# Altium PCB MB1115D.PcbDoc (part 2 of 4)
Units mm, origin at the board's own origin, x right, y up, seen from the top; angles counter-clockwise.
Board outline 66 x 97 mm, 2 copper layers (TOP, Bottom), stack 1.535 mm thick; 198 components, 186 nets, 760 pads, 493 vias.
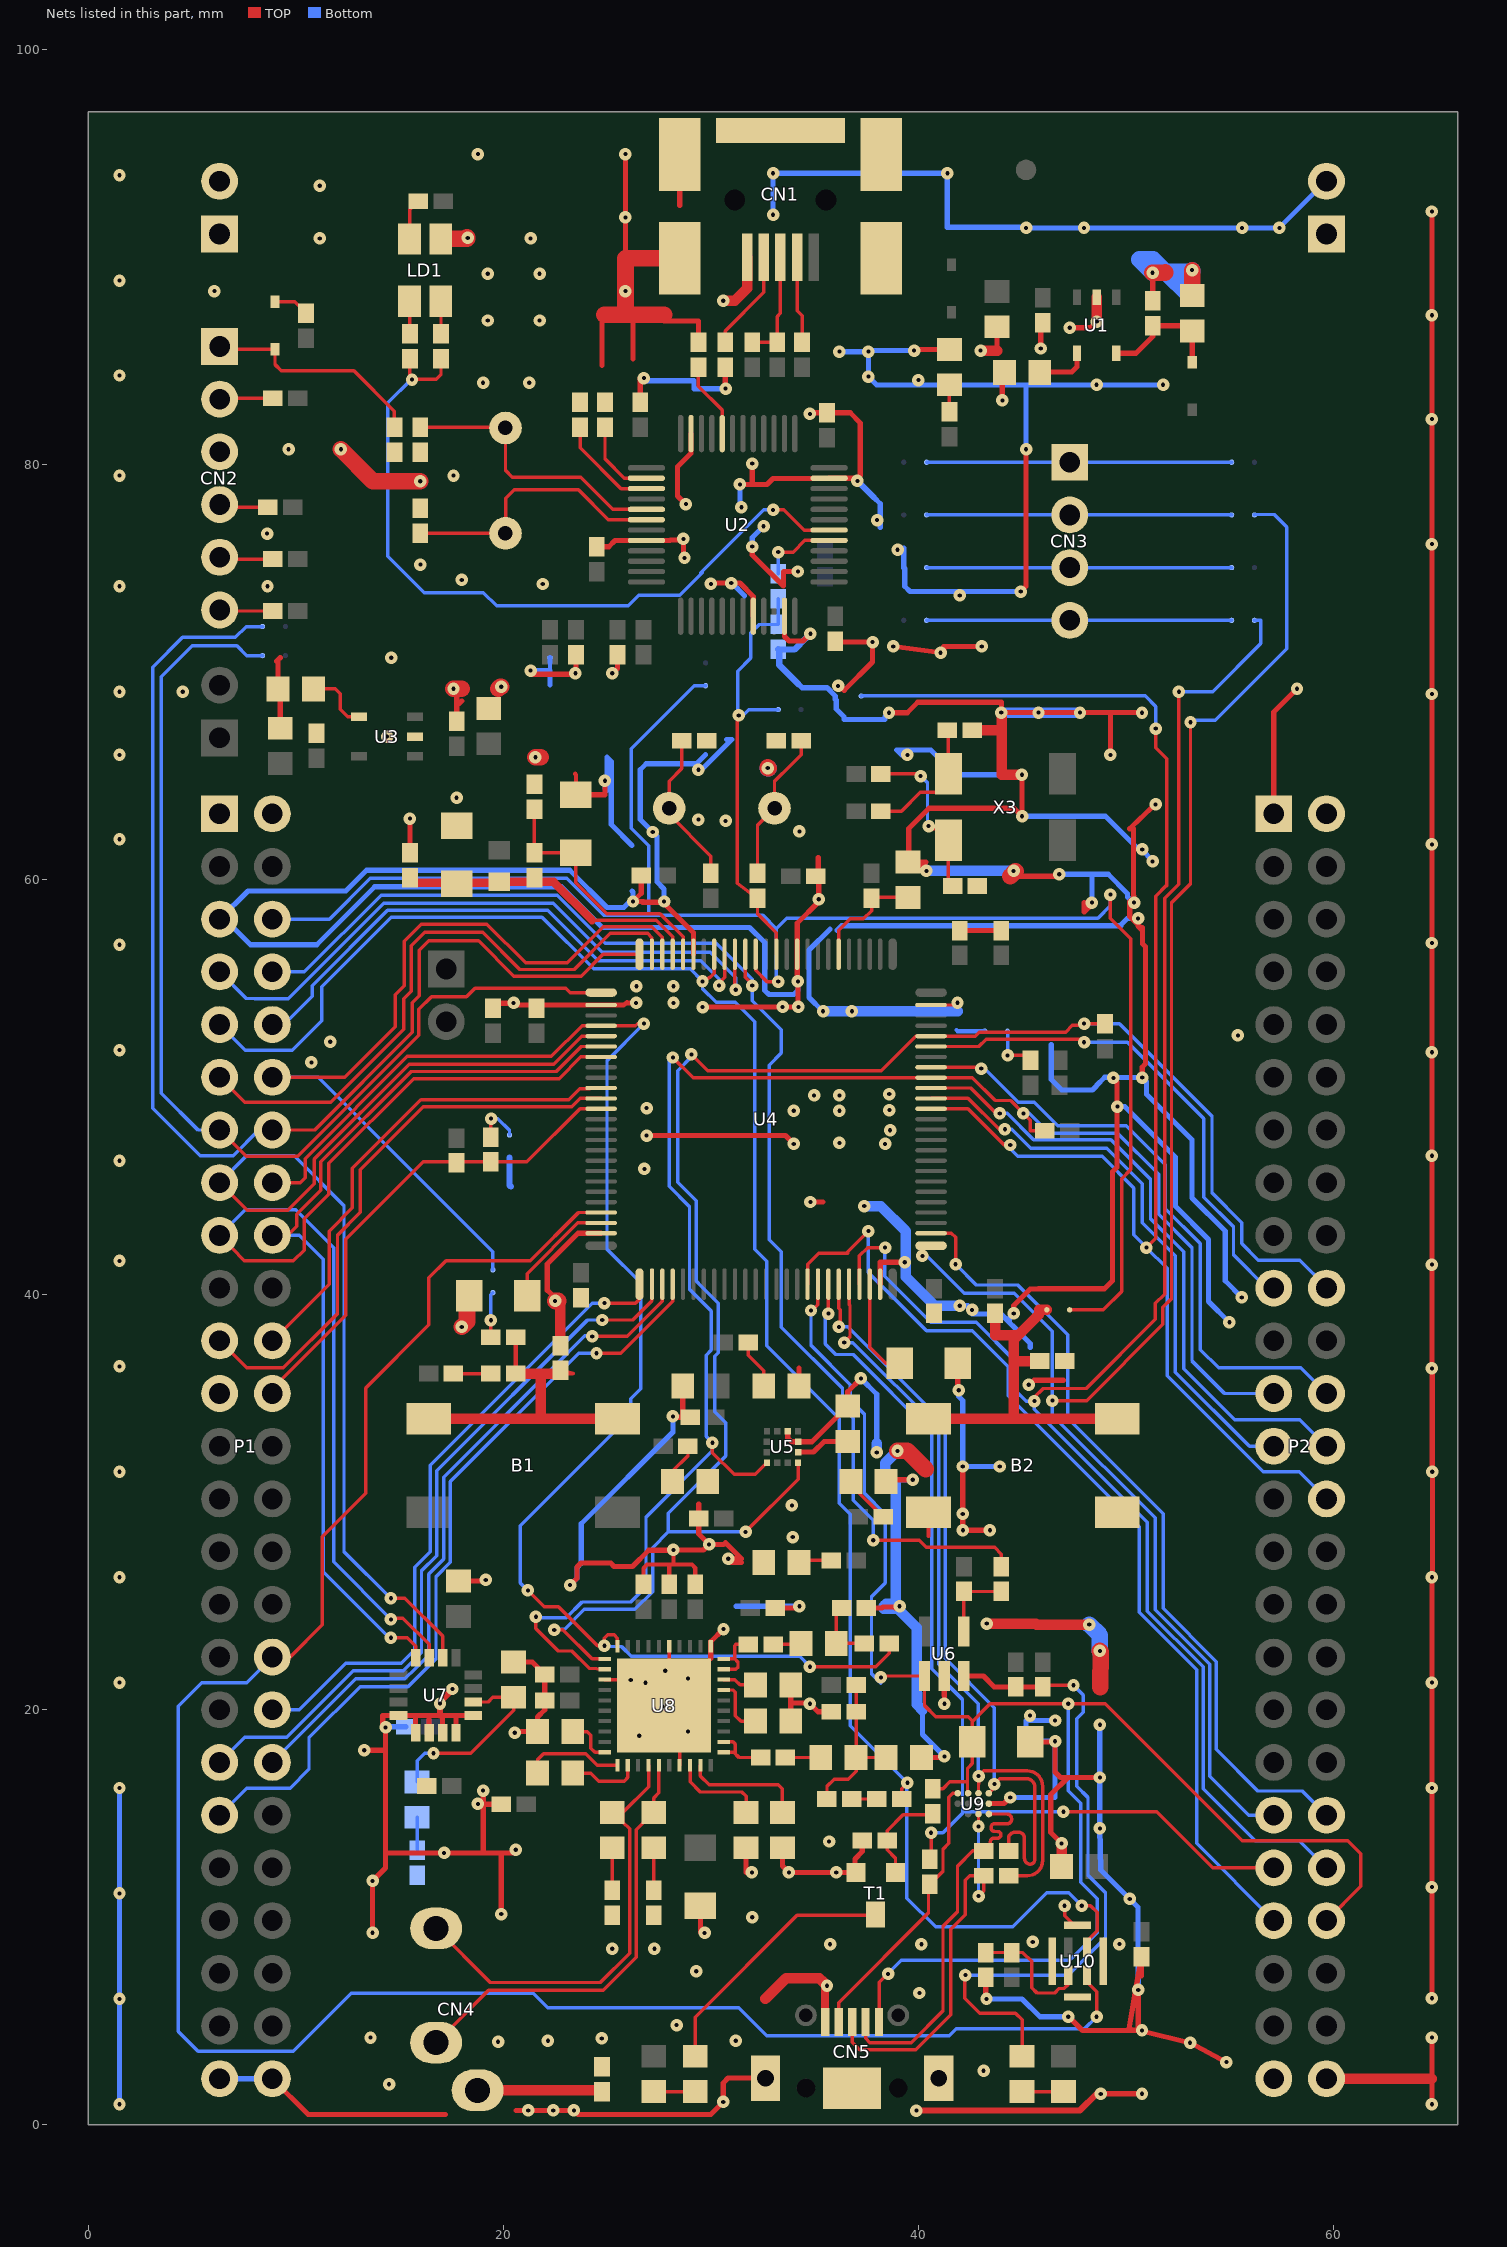
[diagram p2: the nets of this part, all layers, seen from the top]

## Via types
v1: diameter 0.6, hole 0.2, TOP to Bottom, tented both sides, 492 vias
v2: diameter 0.6, hole 0.2, TOP to Bottom, tented bottom, 1 vias

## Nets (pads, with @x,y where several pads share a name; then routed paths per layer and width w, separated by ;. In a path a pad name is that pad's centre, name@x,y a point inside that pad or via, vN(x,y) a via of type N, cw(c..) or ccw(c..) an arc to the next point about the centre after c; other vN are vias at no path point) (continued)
GND: B2.2 B2.3 C1.1 C2.1 C3.1 C4.2 C5.1 C6.1 C7.1 C8.1 C9.1 C10.1 C11.1 C12.2 C13.1 C14.2 C15.1 C16.1 C17.1 C18.1 C19.1 C20.2 C21.1 C22.2 C23.1 C24.2 C25.1 C26.2 C27.2 C28.2 C29.1 C30.1 C31.1 C32.1 C33.2 C34.1 C35.2 C37.1 C38.2 C39.1 C40.1 C41.1 C42.1 C43.1 C44.1 C45.1 C46.1 C48.1 C49.2 C50.1 C51.1 C52.2 C53.1 C54.2 C55.1 C58.2 C59.1 C62.1 C63.1 C64.2 C65.1 C66.1 C67.2 C68.1 CN1.5 CN1.6 CN1.7 CN1.8 CN1.9 CN1.10 CN2.3 CN5.5 CN5.6 CN5.7 CN5.8 JP3.1 JP3.2 JP4.1 JP4.2 LD1.1 LD2.2 LD3.2 LD4.2 LD5.2 LD6.2 P1.1 P1.2 P1.5 P1.23 P1.49 P1.50 P2.1 P2.2 P2.49 P2.50 R5.1 R6.2 R11.1 R12.1 R14.2 R19.1 R35.1 R43.2 R44.2 R50.2 R55.2 R59.2 R60.1 R61.1 R63.1 R68.2 SB6.2 SB12.1 SB19.1 SB20.1 T1.2 U1.2 U2.8 U2.20 U2.23 U2.35 U2.47 U3.2 U4.10 U4.20 U4.27 U4.49 U4.74 U4.99 U5.6 U5.8 U6.2 U7.8 U7.9 U7.10 U7.11 U7.12 U7.13 U8.3 U8.17 U8.31 U8.35 U8.41 U9.D2 U10.5 U10.6 U10.7 U10.8 | length 875.6
  TOP w0.165: U8.3@24.88,21.45 26.025,21.45 U8.41@26.04,21.435 ; U8.41@27.75,21.74 28,21.99 U8.35@28,23.07 ; U8.17@28.5,17.33 28.5,20.2 U8.41@27.75,20.2 28.964,21.414 30,22.45 30,22.476 ; U4.99@40.614,53.962 v1@41.89,53.962 ; v1@41.89,53.947 v1@41.89,53.962 ; v1(41.89,54.074) v1@41.89,53.962 ; v1(47.05,10.553) 47.05,10.08 47.519,9.611 U10.5@47.683,9.611
  TOP w0.2: C6.1@15.931,80.6 C6.1@15.962,80.6 ; 23.47,65.11 23.47,65.09 23.5,65.06 C22.2@23.5,64.097 ; C44.1@26.75,26.05 26.75,26.818 26.929,26.998 28,26.998 ; C45.1@28,26.05 28,26.998 ; v1(28.2,27.7) 28.2,27.683 28.2,26.998 ; C46.1@29.25,26.05 29.25,26.836 29.088,26.998 28.2,26.998 ; 40.49,28.38 B2.2@40.49,29.523 ; 28,26.998 28.2,26.998
  TOP w0.25: P1.50@8.87,2.22 10.599,0.491 17.208,0.491 ; C14.2@9.25,67.3 9.25,69.2 C13.1@9.15,69.2 9.15,70.6 9.075,70.525 9.25,70.7 ; v1(13.3,18.05) 14.331,18.05 ; v1(13.7,9.25) v1(13.7,11.75) ; v1(13.7,11.75) 14.331,12.381 14.331,13.1 ; C23.1@15.5,61.3 v1(15.5,62.948) ; U7.9@15.775,18.9 15.775,19.725 ; U7.10@16.425,18.9 16.425,19.725 ; U7.11@17.075,18.9 17.075,19.725 ; U7.12@17.725,18.9 17.725,19.725 ; C16.1@17.76,67.628 v1@17.76,69.2 ; 17.888,68.501 17.996,68.608 18,68.613 ; U7.13@18.55,19.725 17.725,19.725 ; v1(18.776,15.466) v1@19.03,15.466 ; v1(19.03,16.101) v1@19.03,15.466 ; v1(19.157,26.261) 19.096,26.2 C43.1@17.85,26.2 ; C31.1@19.5,53.8 19.75,54.05 20.5,54.05 20.588,53.962 21.589,53.962 C32.1@21.671,53.962 ; v1(19.9,10.15) 19.9,13.1 ; C59.1@19.9,15.45 v1@19.03,15.45 ; C48.1@20.5,22.3 21.4,22.3 C49.2@22,21.7 C50.1@22,20.45 22,19.998 21.65,19.648 C52.2@21.65,18.95 20.554,18.95 v1(20.554,18.895) ; v1(20.6,13.25) 20.45,13.1 19.9,13.1 ; 20.606,0.691 v1(21.206,0.691) v1(22.405,0.691) v1(23.405,0.691) 23.605,0.491 30.002,0.491 30.592,1.082 30.6,1.089 v1(30.6,1.1) 30.6,2.017 30.833,2.25 CN5.7@32.635,2.25 ; v1(21.316,70.076) 21.316,69.898 23.475,69.898 v1(23.475,69.949) 23.5,69.974 C11.1@23.5,70.85 ; C32.1@21.583,54.05 C32.1@21.671,53.962 ; v1@22.637,39.7 22.116,40.221 22.116,41.476 23.602,42.961 U4.49@24.714,42.962 ; v1(23.221,26.007) 23.551,26.337 23.551,26.883 23.742,27.074 25.177,27.074 25.342,26.909 26.231,26.909 27.006,27.683 v1@28.2,27.683 ; C22.2@23.5,64.097 24.9,64.097 v1(24.9,64.77) v1@24.9,64.8 ; C10.1@24.5,76.05 25.08,76.05 25.38,76.35 28.034,76.35 28.053,76.369 28.625,76.369 v1(28.682,76.426) 28.682,75.562 v1(28.733,75.512) ; v1(24.745,4.163) v1@24.75,4.158 ; 24.75,84.795 24.75,87.221 24.859,87.221 ; v1@25.25,8.484 v1(25.253,8.481) ; v1(25.253,69.949) 25.253,69.936 25.5,70.183 R19.1@25.5,70.85 ; 25.888,89.951 v1(25.888,91.92) v1(25.888,94.968) ; U8.41@26.04,21.435 v1(26.142,21.435) ; 26.25,85.095 26.25,87.221 ; v1(26.403,54.064) 25.958,54.071 25.8,53.962 U4.27@24.714,53.962 C32.1@21.671,53.962 ; C7.1@26.6,83 26.6,84.173 v1(26.777,84.173) ; C25.1@26.65,60.2 26.65,59.35 v1(26.25,58.95) 26.751,58.95 26.714,58.913 v1@27.818,58.913 ; v1(26.904,47.667) 33.6,47.667 v1(34,47.267) ; v1@27.25,8.446 v1(27.285,8.481) ; v1(27.666,20.165) 27.653,20.165 27.66,20.159 27.684,20.134 27.691,20.141 U8.41@27.75,20.2 27.75,21.74 27.75,21.88 v1(27.803,21.88) ; v1(27.75,58.95) 27.754,58.95 27.768,58.963 v1@27.818,58.913 ; 27.75,87.221 27.75,86.92 29.4,86.92 R5.1@29.4,85.9 ; v1@28.15,27.7 v1(28.2,27.7) 29.656,27.7 v1(29.921,27.965) ; v1(28.174,34.135) 28.174,34.097 28.177,34.1 C40.1@28.65,34.1 ; 28.506,92.504 CN1.7@28.506,94.951 ; C37.1@28.65,35.6 C40.1@28.65,34.1 ; v1(28.8,78.1) 28.401,78.499 28.401,79.9 29.05,80.549 U2.47@29.05,81.5 ; C40.1@29,34.1 C40.1@28.65,34.1 ; U4.20@29.164,56.412 29.164,57.449 27.818,58.794 v1@27.818,58.913 ; 29.42,29.923 C42.1@29.42,29.21 29.42,28.467 v1(29.921,27.965) ; C64.2@29.5,10.553 29.5,9.281 29.66,9.281 v1(29.698,9.243) ; v1(29.602,53.864) v1(33.457,53.871) v1@34.2,53.864 ; 30,22.476 30,23.274 v1(30.612,23.886) ; v1(30.002,74.253) 30.048,74.3 31.401,74.3 32.05,73.651 U2.20@32.05,72.7 ; R6.2@30.7,84.7 30.7,83.665 v1(30.714,83.665) ; v1(31.401,79.051) 32.001,79.051 ; 31.476,27.1 30.841,27.1 v1(30.841,27.277) 31.476,27.277 30.703,28.05 30.618,27.965 v1(29.921,27.965) ; C62.1@31.7,13.35 31.7,12.164 v1(31.984,12.164) ; v1(32.001,76.052) 32.001,75.653 33.501,74.152 33.501,74.853 v1(34.199,74.853) ; v1(32.001,80.05) 32.001,79.051 ; R43.2@33.1,24.9 34.179,24.9 v1(34.27,24.991) ; C63.1@33.45,13.35 33.45,12.476 v1(33.762,12.164) v1(36.048,12.164) 36.974,12.164 T1.2@36.976,12.166 ; U2.23@33.55,72.7 33.55,71.714 33.766,71.498 34.443,71.498 v1(34.799,71.855) ; U5.8@33.706,33.426 33.706,33.102 33.894,32.914 U5.6@34.218,32.914 34.88,32.914 C41.1@36.598,34.632 36.598,35.328 v1(37.236,35.966) ; C53.1@33.85,19.45 33.968,19.568 33.85,19.686 33.85,20.33 ; C51.1@33.85,21.194 33.85,20.33 ; 34.164,57.9 U4.10@34.164,56.412 34.164,55.071 v1@34.2,55.034 ; v1(34.2,55.1) v1@34.2,55.034 ; v1(34.219,53.871) v1@34.2,53.864 ; LD3.2@34.25,35.6 34.25,36.475 ; v1(34.778,82.449) 34.829,82.5 C8.1@35.54,82.5 ; v1(34.799,44.468) 35.399,44.468 ; C26.2@35.061,60.17 C26.2@35.182,60.17 ; 35.182,61.07 C26.2@35.182,60.17 ; v1(35.199,59.061) 35.199,60.17 C26.2@35.182,60.17 ; C8.1@35.6,82.5 36.718,82.5 37.204,82.014 37.204,79.474 v1@37.064,79.334 ; U2.35@35.7,79.35 37.064,79.35 v1@37.064,79.334 ; R50.2@35.8,19.9 35.17,19.9 v1(34.778,20.292) 34.816,20.33 33.85,20.33 ; C12.2@36,71.5 36,71.455 v1(37.798,71.455) 37.798,70.498 36.429,69.129 36.429,69.187 36.277,69.187 36.137,69.327 v1(36.137,69.339) ; T1.2@36.997,12.166 T1.2@36.976,12.166 ; v1(37.064,79.22) v1@37.064,79.334 ; R55.2@37.3,13.7 37.3,13.164 36.947,12.812 36.947,12.328 36.891,12.272 36.785,12.166 T1.2@36.976,12.166 ; R44.2@37.5,24.9 38.245,24.9 38.295,24.95 38.845,24.95 38.918,24.877 39.096,24.877 v1(39.096,24.991) ; U4.74@38.164,40.512 38.164,41.564 v1(39.35,41.564) ; LD5.2@38.45,31 38.45,31.087 39.477,31.087 v1(39.731,31.087) ; v1(38.588,68.044) 39.464,68.044 39.972,68.552 44.011,68.552 44.011,68.056 v1(45.793,68.056) v1(47.792,68.056) 49.256,68.056 ; v1(38.791,71.244) 38.86,71.235 41.019,70.947 v1(41.077,70.94) 41.225,70.94 41.225,71.244 v1(43.058,71.244) ; C27.2@39.5,60.85 C27.2@39.541,60.85 ; v1(39.8,85.5) 39.8,85.55 LD2.2@41.5,85.55 ; C58.2@40.15,17.7 41.178,17.7 41.242,17.765 v1(41.255,17.752) ; v1(40.391,60.424) 40.391,60.55 C27.2@40.075,60.55 ; B2.2@40.49,29.523 40.48,29.533 B2.2@40.569,29.533 ; U6.2@41.25,21.625 41.25,20.693 41.255,20.688 v1(41.255,20.292) ; C38.2@41.897,36.7 41.897,35.4 v1(41.95,35.4) ; C29.1@42,57.55 C30.1@44,57.55 ; v1(42.144,31.722) v1(42.144,29.436) 42.144,28.656 v1(42.15,28.65) v1(43.45,28.65) ; R61.1@43.25,7.1 43.25,6.105 v1(43.287,6.068) ; U9.D2@43.4,15.475 44.134,15.475 v1(44.43,15.771) ; 43.8,85.5 C1.1@43.8,86.65 ; v1(44.05,83.1) 44.05,84.45 C5.1@44.15,84.45 ; v1@44.437,60.17 46.647,60.17 46.696,60.218 46.741,60.264 v1(46.793,60.26) ; v1(44.594,60.424) 44.598,60.424 v1@44.684,60.417 ; v1(44.6,39.1) 44.6,39.477 45.394,40.271 45.793,40.271 45.808,40.285 48.977,40.285 49.362,40.67 49.362,45.925 49.577,46.14 v1@49.577,49.251 ; v1(44.938,73.886) 45.192,74.14 v1(45.192,80.744) ; v1(44.994,65.058) 44.994,63.059 44.606,63.447 40.518,63.447 39.541,62.469 C27.2@39.541,60.85 ; v1(45.319,35.659) 45.37,35.659 45.586,35.875 46.995,35.875 ; C54.2@45.397,18.45 v1@46.593,18.45 ; v1(45.9,85.6) 45.9,86.85 C2.1@46,86.85 ; v1(46.593,18.482) v1@46.593,18.45 ; C65.1@46.9,12.45 46.9,12.443 46.938,12.443 C65.1@46.95,12.443 ; v1(46.907,13.561) 46.795,13.673 46.386,14.082 46.386,15.91 47.211,16.736 ; v1@47.235,5.218 47.908,4.544 v1@50.585,4.544 ; v1(47.3,86.6) 48.3,86.6 v1(48.6,86.9) ; 48,58.9 48,58.444 48.411,58.856 v1(48.367,58.9) ; v1(48.748,16.736) 47.211,16.736 ; v1(48.792,1.49) v1(48.792,1.49) 50.704,1.496 v1(50.78,1.496) ; v1(49.256,66.012) 49.256,68.056 ; v1(49.4,50.45) 49.4,50.427 49.577,50.251 v1@49.577,49.251 ; v1(49.592,49.066) 49.591,49.074 v1@49.577,49.251 ; 50.374,59.235 50.374,59.243 ; v1(50.4,58.9) v1@50.4,59.09 ; v1(50.59,58.138) 50.59,57.833 ; v1(50.6,6.5) 50.6,4.724 v1(50.78,4.544) ; 50.75,7.173 C66.1@50.75,8.1 50.478,6.521 50.15,4.616 v1@50.585,4.544 ; v1(50.78,68.044) 50.768,68.056 49.256,68.056 ; v1(50.791,50.465) 50.791,50.965 50.953,51.128 50.953,56.766 50.805,56.914 50.805,57.554 ; 50.805,57.693 50.805,57.617 ; C3.1@51.3,87.9 v1@51.3,89.253 ; v1@51.44,63.624 51.391,63.624 51.348,63.583 50.191,62.459 50.374,62.459 50.374,59.243 ; v1(54.844,3.02) v1(53.1,3.95) 53.006,3.973 v1@50.869,4.497 ; P2.1@57.13,63.18 57.13,68.08 v1(58.25,69.2) ; v1(64.75,0.988) 64.75,2.22 v1(64.75,4.2) v1@64.75,4.3 ; v1(64.75,6.1) v1(64.75,11.45) v1(64.75,16.228) v1(64.75,21.308) v1(64.75,26.388) 64.775,26.388 64.775,31.463 v1(64.77,31.468) 64.77,36.429 v1(64.75,36.449) v1(64.75,41.45) v1(64.75,46.7) v1(64.75,51.689) v1(64.75,56.95) v1(64.75,61.7) v1(64.75,68.95) v1(64.75,76.172) v1(64.75,82.2) v1(64.75,87.2) v1@64.75,92.2 ; 14.331,13.1 14.331,18.05 ; 14.331,13.1 v1(17.15,13.1) 19.03,13.1 ; 14.331,18.05 v1(14.331,19.149) 14.191,19.149 14.191,19.725 U7.8@14.95,19.725 15.775,19.725 ; 15.775,19.725 16.425,19.725 ; 16.425,19.725 16.942,19.725 17.075,19.725 ; 17.075,19.725 17.725,19.725 ; C43.1@17.85,26.2 17.798,26.2 17.798,26.252 C43.1@17.85,26.2 ; 19.03,13.1 19.9,13.1 ; 19.03,13.1 v1@19.03,15.45 ; v1@19.03,15.45 v1@19.03,15.466 ; v1@19.03,15.45 19.014,15.45 v1@19.03,15.466 ; 32.001,79.051 32.712,79.051 33,79.339 35.651,79.339 35.7,79.339 36.998,79.334 v1@37.064,79.334 ; v1@34.2,53.864 v1@34.2,55.034 ; C27.2@39.541,60.85 40.375,60.85 C27.2@40.075,60.55 ; C27.2@39.541,60.85 39.541,60.55 C27.2@40.075,60.55 ; v1@46.593,18.45 46.593,17.003 46.86,16.736 47.211,16.736 ; 50.374,59.243 50.4,59.216 v1@50.4,59.09 ; v1@50.4,59.09 50.336,59.09 50.273,59.027 50.191,58.946 50.191,58.231 50.437,57.986 50.59,57.833 ; v1@50.585,4.544 50.775,4.513 50.794,4.51 v1@50.869,4.497 ; v1@50.585,4.544 v1(50.78,4.544) ; 50.59,57.833 50.59,57.77 50.805,57.554 ; 50.59,57.833 50.805,57.617 ; v1(50.78,4.544) 50.795,4.536 v1@50.869,4.497 ; 50.805,57.554 50.805,57.617
  TOP w0.254: 34.164,57.9 35.199,58.935 v1(35.199,59.061)
  TOP w0.305: 16.942,19.725 16.95,19.733 v1(16.95,20.3) 16.95,20.4 v1(17.55,21) ; v1@39.898,0.691 47.792,0.691 48.592,1.49 v1(48.792,1.49)
  TOP w0.381: CN5.5@35.51,4.95 35.51,6.61 v1(35.6,6.7)
  TOP w0.4: C32.1@21.583,54.05 21.589,53.962 C32.1@21.6,53.8 ; C8.1@35.54,82.5 C8.1@35.6,82.5
  TOP w0.5: v1@22.726,39.7 22.75,39.7 R35.1@22.75,37.55 ; C34.1@23.65,39.7 C34.1@23.677,39.673
  TOP w0.508: C6.1@15.931,80.6 15.962,80.569 C6.1@15.962,80.6 ; v1(30.6,87.9) 31.156,87.9 31.756,88.5 CN1.5@31.756,90.001 ; 32.635,6.078 33.626,7.069 35.231,7.069 35.396,6.904 v1(35.6,6.7) ; C20.2@42.6,67.2 44.011,67.2 ; v1(43,85.5) 43.8,85.5 ; v1(43.3,24.15) 43.307,24.15 45.649,24.153 45.7,24.102 v1(48.24,24.102) v1@48.24,24.153 ; v1@44.011,68.056 44.011,67.2 ; v1(44.994,65.058) 44.011,65.058 44.011,67.2 ; v1(46.907,13.561) 46.907,12.475 46.916,12.466 C65.1@46.938,12.443 ; U1.2@48.599,88.071 v1(48.6,86.9) ; P2.50@59.67,2.22 64.75,2.22
  TOP w0.8: v1(12.172,80.744) 13.716,79.2 v1(16,79.2) ; LD1.1@16.986,90.88 18.25,90.88 v1@18.25,90.95 ; v1(17.6,69.2) 17.76,69.2 18,69.2 ; v1@18,38.45 18.25,38.7 18.25,39.95 C33.2@18.353,39.95 ; v1@19.75,69.2 19.85,69.3 v1(19.9,69.3) ; v1(21.55,65.9) v1@21.8,65.9 ; v1(22.5,39.7) v1@22.637,39.7 ; 24.859,87.221 25.888,87.221 ; 25.888,89.951 25.952,89.951 ; 27.75,87.221 26.25,87.221 25.888,87.221 ; CN1.6@28.506,89.951 25.952,89.951 ; v1(32.746,65.377) 32.784,65.377 32.765,65.396 v1@32.75,65.411 ; C51.1@33.85,21.194 C51.1@33.85,21.2 ; v1(38.997,32.475) 39.474,32.475 40.366,31.582 ; B2.2@40.366,29.566 40.4,29.533 40.49,29.533 B2.2@40.569,29.533 ; v1@44.437,60.17 44.642,60.376 v1@44.684,60.417 ; v1@48.748,22.832 48.792,22.788 48.771,21.093 ; v1(51.288,89.253) 51.3,89.253 51.9,89.265 ; v1(53.193,89.38) 53.2,89.373 C4.2@53.2,88.15 ; 25.888,87.221 v1(25.888,88.364) 25.888,89.888 25.952,89.951
  Bottom w0.165: v1(14.331,19.149) v1@14.359,19.177 ; 41.89,53.664 v1(41.89,54.074)
  Bottom w0.2: 22.24,69.38 22.25,69.39 ; 22.25,70.076 22.25,70.48 ; 41.84,52.75 41.89,52.7 SB19.1@43.2,52.7
  Bottom w0.25: v1(1.504,0.988) v1(1.504,6.068) v1(1.504,11.148) v1(1.504,16.228) ; P1.49@6.33,2.22 P1.50@8.87,2.22 ; v1@14.359,19.177 C68.1@15.31,19.177 ; v1@21.341,70.076 22.25,70.076 22.25,69.39 ; 22.25,70.48 SB12.1@22.25,70.7 ; v1(23.221,26.007) 23.551,26.337 23.551,26.858 23.754,27.061 23.754,28.966 28.174,33.386 ; v1@24.9,64.8 v1(24.9,64.77) 24.9,64.4 25,64.3 25,65.9 25.2,65.7 25.2,62.656 26.2,61.656 ; 26.2,59.461 26.25,59.411 v1(26.25,58.95) 26.171,59.029 25.804,58.661 25.004,58.661 23.205,60.46 13.41,60.46 12.411,59.461 7.691,59.461 P1.5@6.33,58.1 6.575,58.1 7.813,56.862 11.011,56.862 13.81,59.661 22.805,59.661 24.766,57.7 31.87,57.7 32.6,56.97 32.6,54.663 32.8,54.463 34,54.463 34.2,54.663 v1(34.2,55.1) ; v1@26.675,84.046 29.19,84.046 29.19,83.665 v1(30.714,83.665) ; v1(27.75,58.95) 27.75,59.553 27.403,59.9 27.403,62.099 v1(27.2,62.3) 26.6,62.902 26.6,65.3 26.886,65.586 29.31,65.586 29.749,66.025 ; 28.174,33.373 28.174,33.386 ; v1(28.174,34.135) 28.174,33.386 ; v1@29.55,65.3 31.007,66.757 30.765,66.757 ; v1@30.581,23.854 v1(30.612,23.886) ; v1@31,74.3 31.018,74.3 31.628,73.689 ; 31.222,24.991 v1(34.27,24.991) ; v1(31.401,79.051) 31.401,78.025 v1(31.476,77.95) ; v1(32.001,76.052) 32.001,76.493 v1(32.543,77.036) ; v1(33,92.044) v1(33,94.043) 41.396,94.043 41.396,91.445 45.16,91.445 v1(45.192,91.412) v1(47.986,91.412) v1(55.606,91.412) v1@57.384,91.412 ; 34.229,69.426 34.399,69.256 35.599,69.256 36,68.855 36,68.7 36.048,68.652 36.048,68.222 36.413,67.857 36.413,67.714 38.401,67.714 38.401,67.857 v1(38.588,68.044) v1@38.6,68.056 ; v1@34.27,24.864 v1(34.27,24.991) ; v1@34.397,24.991 v1(34.27,24.991) ; 34.585,71.64 v1(34.799,71.855) ; v1@35.399,53.664 34.735,54.328 34.735,56.614 35.738,57.617 ; 36.086,57.566 36.302,57.782 49.764,57.782 49.764,57.833 50.069,58.138 50.221,58.138 ; v1(36.198,85.448) v1(37.598,85.448) ; v1(37.236,35.966) 37.997,35.205 37.997,32.83 ; 37.828,78.456 37.864,78.42 38.169,78.115 38.169,76.976 ; v1@37.997,32.403 v1(38,32.4) ; 38.613,31.087 v1(39.731,31.087) ; 39.299,75.989 SB6.2@39.299,75.041 39.35,74.99 39.35,74.14 39.604,73.886 v1(44.938,73.886) ; v1(39.35,41.564) v1@39.397,41.564 ; v1(39.477,66.012) 39.203,66.012 38.957,66.257 40.596,66.257 41.796,65.058 v1(44.994,65.058) ; v1(39.8,85.5) 37.65,85.5 v1(37.598,85.448) ; 39.95,20.3 39.952,20.298 ; v1@39.996,84.048 v1@39.996,83.848 ; 40.196,19.987 40.196,18.811 v1(41.255,17.752) ; v1(41.95,35.4) 41.95,35.091 42.144,34.897 v1(42.144,31.722) v1(43.922,31.722) ; v1(41.995,39.471) 42.395,39.471 v1(42.595,39.271) 42.595,39.071 43.979,39.071 44.4,38.65 ; v1(43.287,6.068) 45,6.068 45.861,5.207 v1(47.224,5.207) ; v1(44.43,15.771) 46.576,15.771 46.593,15.788 v1(46.593,18.482) 45.194,18.482 45.194,19.481 v1(46.593,19.481) ; v1(44.6,39.1) 44.4,38.9 44.4,38.65 ; v1@44.994,63.059 v1(45,63.059) 49.021,63.059 50.62,61.46 v1(50.791,61.46) v1(51.288,60.881) ; v1(45.192,80.744) 45.192,83.848 ; 45.394,37.472 45.394,37.656 44.635,38.415 44.4,38.65 ; 46.411,52.053 46.411,50.366 46.911,49.866 48.392,49.866 48.592,50.066 48.592,50.083 48.989,50.48 49.4,50.48 v1(49.4,50.45) 49.415,50.465 v1(50.791,50.465) 50.793,50.463 50.991,50.266 50.991,49.666 53.19,47.467 53.19,44.668 54.789,43.069 54.789,40.67 v1(55.588,39.871) ; v1(46.793,60.26) 48.367,60.26 ; v1(48.367,58.9) 48.367,60.26 ; v1(48.748,19.276) v1(48.748,16.736) v1(48.748,14.284) 48.792,12.285 v1(50.191,10.886) 50.198,10.879 50.591,10.486 v1(50.6,6.5) ; v1(49.592,49.066) 49.95,49.066 52.39,46.626 52.39,44.269 53.989,42.669 53.989,39.671 v1(54.989,38.671) ; v1@50.191,59.061 50.089,59.164 50.089,59.326 49.154,60.26 48.367,60.26 ; v1@51.79,83.848 45.192,83.848 ; v1(57.404,91.412) v1@57.384,91.412 ; JP4.2@59.67,93.66 59.632,93.66 57.394,91.422 v1@57.384,91.412 ; v1(37.598,85.448) v1(37.598,84.248) 37.997,83.848 v1@39.996,83.848 ; v1@39.996,83.848 45.192,83.848
  Bottom w0.3: SB20.1@20.3,46.6 20.3,45.28 20.37,45.21 ; v1(37.064,79.22) 37.828,78.456
  Bottom w0.305: C67.2@33.25,71.1 C67.2@33.305,71.093 ; 34.229,69.426 33.305,70.35 C67.2@33.305,71.093 ; 34.585,71.64 34.037,71.093 C67.2@33.305,71.093
  Bottom w0.508: v1@35.399,53.664 v1(35.413,53.664) v1(36.8,53.664) 41.89,53.664 ; v1(37.398,44.269) 38.197,44.269 39.397,43.069 39.397,41.564 39.397,40.87 40.796,39.471 v1(41.995,39.471) ; v1@37.997,32.403 37.997,32.83 ; 38.613,31.087 38.397,30.871 ; v1(38.997,32.475) 38.397,31.875 38.397,30.871 ; v1(39.096,24.991) 39.096,24.864 v1@39.007,24.864 ; 39.952,20.298 39.952,20.782 39.922,20.813 ; 40.196,19.987 39.922,20.262 39.922,20.813 ; v1(40.391,60.424) v1(44.594,60.424) ; v1(43.994,68.056) v1(45.793,68.056) v1(47.792,68.056) ; 38.334,24.991 38.397,25.054 38.461,25.054 ; 38.334,24.991 38.334,24.864 v1@39.007,24.864 ; 38.334,24.991 38.461,24.991 38.461,25.054 ; 38.397,30.871 38.906,30.871 38.906,25.054 v1@38.88,25.054 ; 38.461,25.054 38.461,25.118 38.88,25.118 v1@38.88,25.054 ; 38.461,25.054 v1@38.88,25.054 ; v1@38.88,25.054 38.88,24.991 v1@39.007,24.864 ; v1@39.007,24.864 39.922,23.95 39.922,20.813
  Bottom w0.8: v1(32.746,65.377) v1@32.784,65.377 ; v1(48.24,24.102) 48.748,23.594 v1(48.748,22.835) v1@48.748,22.832 ; v1(51.288,89.253) v1@51.25,89.291 ; 53.079,88.123 51.91,89.291 ; v1(53.193,89.38) 53.193,89.291 51.91,89.291 ; v1@51.25,89.291 51.91,89.291 ; v1@51.25,89.291 50.653,89.888 51.313,89.888 51.91,89.291
  other v1: 39.909,0.686 14.5,1.95 43.15,2.6 19.75,4 22.149,4.05 31.2,4.05 13.6,4.2 28.35,4.8 40.05,6.35 29.3,7.4 35.75,8.7 40.15,8.7 49.688,8.707 45.517,8.814 32,10 35.7,13.65 26.55,18.75 28.9,18.95 45.383,19.72 1.504,21.308 26.85,21.3 28.9,21.5 1.504,26.388 33.909,29.845 1.504,31.468 1.504,36.548 18,38.453 1.504,41.628 26.803,46.068 1.504,46.454 38.397,47.267 36.2,47.318 38.639,47.927 34,48.866 36.198,48.866 38.608,48.895 26.904,48.994 34.981,49.604 36.198,49.604 38.597,49.666 10.75,51.2 1.504,51.788 11.664,52.194 55.4,52.5 20.5,54.064 28.202,54.064 26.416,54.864 28.2,54.864 1.504,56.868 1.504,61.948 34.27,62.329 30.714,62.837 29.4,62.9 51.435,63.627 17.75,63.95 29.4,65.3 1.504,66.012 14.4,66.9 1.504,69.06 4.552,69.06 14.6,70.7 42,73.7 1.504,74.14 8.636,74.14 21.9,74.25 30.988,74.295 18,74.45 16.002,75.184 39,75.9 8.616,76.68 38.017,77.328 1.504,79.474 17.6,79.474 9.652,80.744 48.592,83.85 51.8,83.85 19.03,83.947 21.25,83.95 40.005,84.074 1.504,84.3 19.25,86.95 21.75,86.95 6.076,88.364 1.504,88.872 19.25,89.2 21.75,89.2 11.156,90.904 21.316,90.904 18.288,90.932 64.75,92.202 11.156,93.444 1.504,93.952 41.402,94.043 18.776,94.968
  other v2: 33.953,28.321
LED_STLINK: R3.1 R4.1 U2.30 | length 37
  TOP w0.165: R3.1@15.5,85.1 15.5,84.2 v1(15.6,84.1) 15.622,84.122 16.771,84.122 17,84.351 R4.1@17,85.1 ; v1(33,77.823) 33.521,77.823 34.494,76.85 U2.30@35.7,76.85
  Bottom w0.165: v1(15.6,84.1) 15.553,84.1 14.433,82.979 14.433,75.591 16.188,73.835 19.043,73.835 19.678,73.2 26.015,73.2 26.523,73.708 28.504,73.708 29.584,74.788 29.52,74.788 32.556,77.823 v1(33,77.823)
MCO: C67.1 R25.1 R66.2 SB14.1 U4.12 | length 21.7
  TOP w0.165: v1(31.349,67.917) 31.552,67.917 31.273,67.638 31.273,59.827 R25.1@32.25,59.1 32.25,58.355 33.164,57.441 U4.12@33.164,56.412
  Bottom w0.165: v1(31.349,67.917) v1@31.349,67.968 ; SB14.1@33.25,68.2 31.835,68.2 31.603,67.968 v1@31.349,67.968 ; R66.2@33.25,73.55 C67.1@33.25,72.3 32.328,72.3 31.933,71.905 31.933,70.686 31.298,70.051 31.298,67.968 v1@31.349,67.968
NetB1_2: B1.2 B1.3 C36.1 R34.2 R35.2 | length 16.4
  TOP w0.2: C36.1@20.6,36.2 R34.2@20.6,37.95 ; 22.345,36.2 23.35,36.2 R35.2@22.75,36.35
  TOP w0.5: B1.3@16.41,34.023 21.811,34.023 ; C36.1@20.6,36.2 21.811,36.2 ; 22.345,36.2 21.811,36.2 ; B1.2@25.51,34.023 21.811,34.023 ; 21.811,34.023 21.811,36.2
NetB2_1: B2.1 B2.4 C39.2 R33.1 SB1.2 | length 18.7
  TOP w0.5: B2.1@40.49,34.023 44.582,34.023 ; R33.1@43.7,39.1 43.7,38.047 44.824,38.047 ; C39.2@45.85,36.8 44.618,36.8 44.608,36.789 ; SB1.2@46.193,39.271 45.814,39.271 45.814,39.037 44.824,38.047 ; B2.4@49.59,34.023 44.582,34.023 ; 44.582,34.023 44.608,34.048 44.608,36.789 ; 44.608,36.789 44.608,37.831 44.824,38.047
NetC3_2: C3.2 C4.1 D3.1 U1.5 | length 6.1
  TOP w0.25: U1.5@49.549,85.371 50.492,85.371 51.3,86.179 C3.2@51.3,86.7 52.911,86.7 53.155,86.456 C4.1@53.2,86.45 D3.1@53.2,84.943
NetC5_2: C5.2 U1.4 | length 2.6
  TOP w0.25: C5.2@45.85,84.45 45.865,84.465 47.395,84.465 47.649,84.719 U1.4@47.649,85.371
NetC13_2: C13.2 U3.4 | length 3.2
  TOP w0.165: C13.2@10.85,69.2 11.905,69.2 12.147,68.958 12.147,68.209 12.506,67.85 U3.4@13.05,67.85
NetC18_2: C18.2 R24.1 X2.1 | length 7.5
  TOP w0.165: C18.2@28.6,66.7 28.6,65.359 27.991,64.749 X2.1@27.991,63.445 27.991,63.147 30,61.138 R24.1@30,60.3
NetC19_2: C19.2 R25.2 X2.2 | length 7.3
  TOP w0.165: R25.2@32.25,60.3 32.25,62.624 X2.2@33.071,63.445 33.071,64.737 33.902,65.567 34.35,66.016 C19.2@34.35,66.7
NetC20_1: C20.1 R22.2 X3.4 | length 6.6
  TOP w0.165: R22.2@38.2,63.3 39.191,63.3 40.099,64.209 41.45,64.209 X3.4@41.45,65.1 41.45,66.9 C20.1@41.4,67.2
NetC21_2: C21.2 C22.1 R23.1 U4.21 | length 12.6
  TOP w0.165: C21.2@21.5,63.4 R23.1@21.5,61.3 C22.1@23.5,61.3 ; C22.1@23.5,61.303 C22.1@23.5,61.3 ; U4.21@28.664,56.412 28.664,57.255 27.552,58.367 24.986,58.367 23.5,59.853 C22.1@23.5,61.3
NetC23_2: C23.2 C24.1 L1.2 R23.2 U4.22 | length 15.2
  TOP w0.165: C23.2@15.5,60.1 C23.2@15.671,59.929 ; C24.1@17.75,59.803 C24.1@17.75,59.85 ; L1.2@19.807,59.865 L1.2@19.807,59.898 ; R23.2@21.5,60.1 R23.2@21.7,59.898 ; 24.275,58.049 27.374,58.049 28.164,57.259 U4.22@28.164,56.412 ; R23.2@21.7,59.898 21.748,59.85 R23.2@21.7,59.898
  TOP w0.4: C23.2@15.671,59.929 15.75,59.85 17.75,59.85 19.792,59.85 L1.2@19.807,59.865 ; L1.2@19.807,59.898 21.7,59.898 22.426,59.898 24.275,58.049
NetC27_1: C27.1 R26.2 U4.6 | length 5.5
  TOP w0.165: U4.6@36.164,56.412 36.164,57.555 36.721,58.113 37.356,58.113 37.75,58.506 R26.2@37.75,59.1 37.8,59.15 C27.1@39.5,59.15
NetC28_1: C28.1 R21.2 X3.1 | length 8.9
  TOP w0.165: R21.2@38.2,65.1 39.416,65.1 39.426,65.11 40.112,65.11 v1(40.112,64.996) ; v1(40.493,62.583) 40.372,62.583 40.372,62.45 41.45,62.45 X3.1@41.45,61.9 41.45,59.7 C28.1@41.65,59.7
  Bottom w0.165: v1(40.112,64.996) 40.442,64.666 40.442,62.583 v1(40.493,62.583)
NetC33_1: C33.1 U4.48 | length 5.6
  TOP w0.165: C33.1@21.147,39.95 21.147,41.015 23.594,43.462 U4.48@24.714,43.462
NetC36_2: C36.2 R37.1 | length 1.8
  TOP w0.165: R37.1@17.6,36.2 C36.2@19.4,36.2
NetC38_1: C38.1 U4.73 | length 4.8
  TOP w0.165: U4.73@37.664,40.512 37.664,37.46 38.423,36.7 C38.1@39.103,36.7
NetC41_2: C41.2 U5.5 | length 2.6
  TOP w0.25: U5.5@34.218,32.414 34.954,32.414 35.472,32.932 C41.2@36.598,32.932
NetC47_1: C47.1 R45.1 | length 1.4
  TOP w0.165: R45.1@33,23.15 34.35,23.15 C47.1@34.35,23.2
NetC47_2: C47.2 R44.1 R46.1 | length 3.2
  TOP w0.165: R44.1@36.3,24.9 36.05,24.65 C47.2@36.05,23.2 R46.1@37.4,23.2
NetC48_2: C48.2 C69.1 U7.14 | length 9.4
  TOP w0.165: v1(16.637,17.907) 18.44,17.907 20.5,19.967 C48.2@20.5,20.6 19.497,20.6 19.494,20.603 19.265,20.375 U7.14@18.55,20.375
  Bottom w0.165: C69.1@15.85,16.522 15.85,17.551 16.205,17.907 v1(16.637,17.907)
NetC51_2: C51.2 U8.28 | length 1.6
  TOP w0.165: U8.28@30.62,21.45 31.156,21.45 31.406,21.2 C51.2@32.15,21.2
NetC52_1: C52.1 U8.10 | length 2.3
  TOP w0.165: C52.1@23.35,18.95 24.042,18.95 24.224,18.768 24.224,18.146 24.42,17.95 U8.10@24.88,17.95
NetC53_2: C53.2 U8.27 | length 2.8
  TOP w0.165: U8.27@30.62,20.95 31.072,20.95 31.184,20.838 31.184,19.72 31.454,19.45 C53.2@32.15,19.45
NetC56_1: C56.1 U8.12 | length 3.5
  TOP w0.165: C56.1@23.35,16.95 24.213,16.95 24.605,16.558 25.825,16.558 26,16.734 U8.12@26,17.33
NetC56_2: C56.2 U8.11 | length 4.8
  TOP w0.165: C56.2@21.65,16.95 21.65,17.591 21.938,17.879 23.97,17.879 24.519,17.33 U8.11@25.5,17.33
NetC57_1: C57.1 R51.1 | length 1.7
  TOP w0.165: R51.1@33.6,17.7 C57.1@35.3,17.7
NetC57_2: C57.2 C58.1 R47.1 R50.1 R52.1 | length 8
  TOP w0.165: R52.1@35.6,15.7 35.6,16.313 35.946,16.66 36.619,16.66 37,17.041 C57.2@37,17.7 ; R50.1@37,19.9 36.975,19.9 37,19.925 R50.1@37,19.962 ; R47.1@37,21.2 R50.1@37,19.962 ; C58.1@38.45,17.7 C57.2@37,17.7 ; C57.2@37,17.7 R50.1@37,19.962
NetC60_1: C60.1 CN4.3 U8.14 | length 21.2
  TOP w0.165: CN4.3@16.76,9.46 19.365,6.855 24.682,6.855 26.091,8.265 26.091,14.259 25.764,14.587 C60.1@25.764,15.05 ; C60.1@25.25,15.05 C60.1@25.764,15.05 ; U8.14@27,17.33 27,16.286 C60.1@25.764,15.05
NetC60_2: C60.2 R59.1 | length 2
  TOP w0.165: R59.1@25.25,11.3 C60.2@25.25,13.35
NetC61_1: C61.1 CN4.2 U8.15 | length 21.1
  TOP w0.165: CN4.2@16.76,3.96 19.287,6.487 24.821,6.487 26.409,8.075 26.409,14.209 C61.1@27.25,15.05 27.25,15.748 27.5,15.999 U8.15@27.5,17.33
NetC61_2: C61.2 R60.2 | length 2
  TOP w0.165: R60.2@27.25,11.3 C61.2@27.25,13.35
NetC62_2: C62.2 U8.18 | length 4.6
  TOP w0.165: U8.18@29,17.33 29,16.532 29.495,16.037 31.501,16.037 31.7,15.839 C62.2@31.7,15.05
NetC63_2: C63.2 U8.19 | length 5.9
  TOP w0.165: U8.19@29.5,17.33 29.5,16.807 29.927,16.38 33.254,16.38 33.45,16.184 C63.2@33.45,15.05
NetC69_2: C69.2 R68.1 | length 1.6
  Bottom w0.165: R68.1@15.85,13.224 C69.2@15.85,14.822
NetCN1_2: CN1.2 R9.1 | length 4.2
  TOP w0.165: CN1.2@34.156,90.001 34.156,87.424 34.4,87.18 R9.1@34.4,85.9
NetCN1_3: CN1.3 R7.1 R8.1 | length 5.4
  TOP w0.165: R7.1@32.048,85.9 R8.1@33.2,85.9 33.2,87.142 33.356,87.298 CN1.3@33.356,90.001
  TOP w0.25: R7.1@32,85.9 R7.1@32.048,85.9
NetCN1_4: CN1.4 R6.1 | length 4.9
  TOP w0.165: R6.1@30.7,85.9 30.7,86.445 32.556,88.301 CN1.4@32.556,90.001
NetCN2_1: CN2.1 D2.1 R14.1 | length 11
  TOP w0.165: CN2.1@6.33,85.7 6.33,85.557 D2.1@9,85.557 9,84.83 9.302,84.529 12.807,84.529 14.75,82.586 R14.1@14.75,81.8
NetCN2_2: CN2.2 R10.1 | length 2.6
  TOP w0.165: CN2.2@6.33,83.16 6.33,83.2 R10.1@8.9,83.2
NetCN2_4: CN2.4 R15.1 | length 2.4
  TOP w0.165: CN2.4@6.33,78.08 6.33,77.95 R15.1@8.65,77.95
NetCN2_5: CN2.5 R16.1 | length 2.7
  TOP w0.165: CN2.5@6.33,75.54 6.33,75.45 R16.1@8.9,75.45
NetCN2_6: CN2.6 R17.1 | length 2.6
  TOP w0.165: CN2.6@6.33,73 6.33,72.95 R17.1@8.9,72.95
NetCN3_1: CN3.1 SB2.1 SB3.2 | length 14.7
  Bottom w0.165: SB2.1@40.399,80.121 47.026,80.121 47.046,80.101 47.299,80.1 CN3.1@47.299,80.121 SB3.2@55.099,80.121
NetCN3_2: CN3.2 SB4.1 SB5.2 | length 14.7
  Bottom w0.165: SB4.1@40.4,77.581 41.014,77.581 CN3.2@47.299,77.581 SB5.2@55.099,77.581
NetCN3_3: CN3.3 SB6.1 SB7.2 | length 14.7
  Bottom w0.165: SB6.1@40.399,75.041 CN3.3@47.299,75.041 SB7.2@55.099,75.041
NetCN3_4: CN3.4 SB8.1 SB9.2 | length 21.6
  Bottom w0.165: SB9.2@55.099,72.501 CN3.4@47.299,72.501 ; CN3.4@47.299,72.501 SB8.1@40.399,72.501 40.401,72.501 CN3.4@47.299,72.501
NetCN4_1: CN4.1 R63.2 | length 6
  TOP w0.5: CN4.1@18.76,1.66 24.69,1.66 R63.2@24.75,1.6
NetCN5_2: CN5.2 R56.1 U9.D1 | length 18.7
  TOP w0.165: CN5.2@37.46,4.95 37.46,4.161 37.661,3.96 39.655,3.96 41.192,5.496 41.192,9.56 41.89,10.259 41.89,12.462 42.628,13.2 R56.1@43.15,13.2 43.478,13.2 43.478,13.65 cw(c43.643,13.65) 43.643,13.815 43.82,13.815 ccw(c43.82,13.98) 43.986,13.98 ccw(c43.833,13.98) 43.833,14.132 43.693,14.132 cw(c43.693,14.323) 43.503,14.323 cw(c43.693,14.323) 43.693,14.514 44.303,14.513 ccw(c44.303,14.704) 44.494,14.704 44.494,14.759 ccw(c44.278,14.759) 44.278,14.975 U9.D1@43.4,14.975
NetCN5_3: CN5.3 R58.1 U9.C1 | length 19.4
  TOP w0.165: CN5.3@36.81,4.95 36.81,3.972 37.166,3.617 39.883,3.617 41.573,5.306 41.573,9.421 42.271,10.119 42.271,11.783 42.488,12 R58.1@43.15,12 43.15,11.265 v1(42.906,11.021) ; v1(42.9,14.381) U9.C1@42.9,14.975
  Bottom w0.165: v1(42.9,14.381) 42.9,11.027 v1(42.906,11.021)
NetCN5_4: CN5.4 R57.2 U9.A3 | length 13.6
  TOP w0.165: CN5.4@36.16,4.95 36.16,5.888 40.493,10.221 40.493,11.6 40.577,11.6 41.192,12.215 41.192,13.282 41.471,13.561 41.471,15.785 41.661,15.975 U9.A3@41.9,15.975
NetD2_2: D2.2 R2.1 | length 1.7
  TOP w0.165: D2.2@9,87.843 9.957,87.843 R2.1@10.5,87.3
NetLD1_2: LD1.2 R4.2 | length 1.6
  TOP w0.165: LD1.2@16.986,87.88 17,87.88 R4.2@17,86.3
NetLD1_3: LD1.3 R3.2 | length 1.6
  TOP w0.165: LD1.3@15.486,87.88 15.5,87.866 R3.2@15.5,86.3
NetLD1_4: LD1.4 R1.1 | length 2
  TOP w0.165: LD1.4@15.486,90.88 15.486,92.286 R1.1@15.9,92.7
NetLD2_1: LD2.1 R13.1 | length 1.3
  TOP w0.165: R13.1@41.5,82.55 LD2.1@41.5,83.85
NetLD3_1: LD3.1 R36.1 | length 2.4
  TOP w0.165: R36.1@31.8,37.7 31.8,37.088 32.55,36.338 LD3.1@32.55,35.6
NetLD4_1: LD4.1 R38.1 | length 2
  TOP w0.165: LD4.1@28.15,31 28.15,31.495 28.9,32.245 R38.1@28.9,32.7
NetLD5_1: LD5.1 R39.1 | length 2.3
  TOP w0.165: LD5.1@36.75,31 36.75,30.85 R39.1@38.3,29.3
NetLD6_1: LD6.1 R40.1 | length 1.6
  TOP w0.165: LD6.1@34.25,27.1 34.25,27.163 34.287,27.2 R40.1@35.8,27.2
NetLD7_1: LD7.1 R64.1 | length 2
  TOP w0.165: R64.1@27.25,1.6 LD7.1@29.25,1.6
NetLD7_2: LD7.2 T1.3 | length 12.6
  TOP w0.165: LD7.2@29.25,3.3 29.25,5.188 34.156,10.094 37.937,10.094 T1.3@37.937,10.134
NetLD8_1: LD8.1 R65.1 | length 2
  TOP w0.165: LD8.1@45,1.6 R65.1@47,1.6
NetLD8_2: LD8.2 R48.1 R49.2 U6.3 | length 32.6
  TOP w0.165: v1(42.271,7.211) 42.246,7.186 42.246,6.093 42.97,5.369 44.684,5.369 45,5.054 LD8.2@45,3.3 ; R49.2@45.992,21.1 45.992,21.13 45.992,21.181 v1(47.478,21.181)
  TOP w0.25: U6.3@42.2,21.625 43.135,21.625 43.66,21.1 45.962,21.1 R49.2@45.992,21.13 ; R49.2@45.992,21.1 R49.2@46,21.1
  Bottom w0.165: v1(42.271,7.211) 42.271,7.44 42.5,7.211 47.216,7.211 49.022,9.017 49.022,11.176 48.177,12.021 48.177,15.771 47.63,16.317 47.63,19.568 47.948,19.886 47.948,20.711 v1(47.478,21.181)
NetR5_2: R5.2 U2.44 | length 3.7
  TOP w0.165: R5.2@29.4,84.7 29.4,83.785 30.55,82.635 U2.44@30.55,81.5
NetR11_2: R11.2 U2.3 | length 5
  TOP w0.165: R11.2@23.7,81.8 23.7,80.824 25.674,78.85 U2.3@26.9,78.85
NetR12_2: R12.2 U2.2 | length 3.9
  TOP w0.165: R12.2@24.9,81.8 24.9,80.284 25.834,79.35 U2.2@26.9,79.35
NetR28_1: R28.1 SB19.2 | length 2.5
  TOP w0.165: v1(44.303,51.534) 45.332,51.534 45.4,51.534 R28.1@45.4,51.3
  Bottom w0.165: SB19.2@44.3,52.7 44.303,52.7 v1(44.303,51.534)
NetR31_2: R31.2 SB20.2 | length 2.4
  TOP w0.165: R31.2@19.4,47.6 19.4,48.57 19.411,48.57 v1(19.411,48.486)
  Bottom w0.165: v1(19.411,48.486) 19.741,48.486 20.3,47.927 SB20.2@20.3,47.7
NetR34_1: R34.1 SB21.2 | length 2.2
  TOP w0.165: R34.1@19.4,37.95 v1(19.4,38.772)
  Bottom w0.165: v1(19.4,38.772) 19.4,40 SB21.2@19.5,40.1
NetR41_2: R41.2 R42.2 U6.4 | length 3.7
  TOP w0.165: U6.4@42.2,23.775 R41.2@42.2,25.7 R42.2@44,25.7
NetR45_2: R45.2 U8.29 U8.30 | length 3.1
  TOP w0.165: U8.29@30.62,21.95 31.204,21.95 31.311,22.057 31.311,22.298 31.159,22.45 31.133,22.45 ; U8.30@30.62,22.45 31.133,22.45 ; R45.2@31.8,23.15 31.209,23.15 31.146,23.086 31.146,22.463 31.133,22.45
NetR51_2: R51.2 U8.21 U8.22 | length 2.9
  TOP w0.165: U8.21@30.62,17.95 31.108,17.95 ; U8.22@30.62,18.45 31.07,18.45 31.171,18.348 31.171,17.95 31.108,17.95 ; R51.2@32.4,17.7 31.358,17.7 31.108,17.95
NetR52_2: R52.2 R53.1 | length 1.2
  TOP w0.165: R52.2@36.8,15.7 R53.1@38,15.7
NetR54_1: R54.1 R55.1 T1.1 | length 4.7
  TOP w0.165: T1.1@38.902,12.166 38.902,12.853 38.5,13.255 38.5,14.171 39.261,14.933 40.633,14.933 R54.1@40.7,15
NetR61_2: R61.2 R62.1 U10.2 | length 6.2
  TOP w0.165: R61.2@43.25,8.3 R62.1@44.5,8.3 45.04,8.3 45.466,7.874 45.466,6.604 45.72,6.35 46.582,6.35 46.8,6.569 47.041,6.569 47.233,6.761 U10.2@47.233,7.211
NetR66_1: R66.1 U2.29 | length 3.7
  TOP w0.165: v1(33.25,75.787) 33.974,75.787 34.537,76.35 U2.29@35.7,76.35
  Bottom w0.165: R66.1@33.25,74.75 v1(33.25,75.787)
NRST: P1.6 SB1.1 SB13.2 U4.14 | length 83.8
  TOP w0.165: U4.14@32.164,56.412 32.164,55.634 32.708,55.09 v1(33.254,55.09) ; SB1.1@47.293,39.271 48.916,39.271 49.8,40.155 49.8,45.588 50.247,46.035 50.247,57.147 49.256,58.138 v1(49.256,59.281)
  Bottom w0.165: P1.6@8.87,58.1 11.626,58.1 13.594,60.068 23.056,60.068 24.847,58.278 27.018,58.278 ; SB13.2@29.75,69.35 29.201,69.35 26.167,66.317 26.167,62.481 27.018,61.63 27.018,58.278 ; v1(33.254,55.09) 33.127,55.09 33.152,55.115 33.152,57.643 ; v1(49.256,59.281) 49.256,58.748 48.659,58.151 33.66,58.151 33.152,57.643 ; 27.018,58.278 32.517,58.278 33.152,57.643
OSC_IN: C6.2 U2.5 X1.2 | length 13.7
  TOP w0.165: C6.2@16,81.8 20.076,81.8 X1.2@20.105,81.771 20.105,79.732 20.44,79.398 23.729,79.398 25.277,77.85 U2.5@26.9,77.85
OSC_OUT: C9.2 U2.6 X1.1 | length 13.4
  TOP w0.165: C9.2@16,76.7 16,76.691 X1.1@20.105,76.691 20.122,76.708 20.122,78.392 20.518,78.788 23.626,78.788 25.064,77.35 U2.6@26.9,77.35
PA0: P1.12 SB21.1 U4.23 | length 41.5
  TOP w0.165: P1.12@8.87,50.48 12.363,50.48 14.795,52.912 14.795,54.463 15.22,54.889 15.22,57.033 16.049,57.862 19.207,57.862 21.077,55.992 23.073,55.992 24.813,57.732 27.158,57.732 27.664,57.226 U4.23@27.664,56.412
  Bottom w0.165: P1.12@8.87,50.48 11.092,50.48 19.5,42.072 SB21.1@19.5,41.2
PA1: P1.11 U4.24 | length 29.2
  TOP w0.165: P1.11@6.33,50.48 7.544,49.266 11.682,49.266 15.209,52.793 15.209,54.263 15.563,54.617 15.563,56.816 16.209,57.462 19.007,57.462 20.795,55.674 23.416,55.674 25.156,57.414 26.96,57.414 27.164,57.211 U4.24@27.164,56.412
PA2: P1.14 SB10.1 U4.25 | length 59.3
  TOP w0.165: P1.14@8.87,47.94 10.906,47.94 15.609,52.643 15.609,54.064 15.957,54.411 15.957,56.61 16.408,57.062 18.807,57.062 20.513,55.357 23.749,55.357 24.804,56.412 U4.25@26.564,56.412
  Bottom w0.165: SB10.1@8.4,72.2 7.603,72.2 7.079,71.676 4.539,71.676 3.104,70.241 3.104,48.994 5.403,46.695 6.978,46.695 8.222,47.94 P1.14@8.87,47.94
PA3: P1.13 SB11.1 U4.26 | length 52.4
  TOP w0.165: P1.13@6.33,47.94 7.603,46.667 10.099,46.667 15.931,52.499 15.931,53.752 16.541,54.362 18.226,54.362 18.636,54.772 23.01,54.772 23.221,54.562 U4.26@24.714,54.562
  Bottom w0.165: P1.13@6.33,47.94 5.288,47.94 3.523,49.705 3.523,69.784 5.009,71.27 7.168,71.27 7.638,70.8 SB11.1@8.4,70.8
PA4: P1.16 R46.2 U4.29 U8.40 | length 74.1
  TOP w0.165: P1.16@8.87,45.4 10.212,45.4 10.449,45.637 10.449,46.56 15.372,51.483 22.319,51.483 23.798,52.962 U4.29@24.714,52.962 26.369,52.962 26.471,53.064 v1(26.777,53.064) ; v1(21.189,25.753) 21.976,24.966 22.662,24.966 24.542,23.086 v1(24.872,23.086) 24.872,23.454 25.024,23.607 25.348,23.607 25.5,23.454 U8.40@25.5,23.07 ; v1(34.778,22.07) 37.95,22.07 38.6,22.72 R46.2@38.6,23.2
  Bottom w0.165: v1(21.189,25.753) 21.176,25.753 20.821,26.109 20.821,28.877 26.142,34.198 26.142,34.986 26.625,35.468 26.625,40.574 24.999,42.199 24.999,51.286 v1(26.777,53.064) ; v1(24.872,23.086) 24.872,23.048 25.698,23.048 26.167,22.578 34.283,22.578 34.778,22.083 v1(34.778,22.07)
PA5: P1.15 U4.30 U7.2 | length 54.8
  TOP w0.165: P1.15@6.33,45.4 7.654,44.076 9.612,44.076 10.887,45.351 10.887,46.541 15.461,51.115 22.434,51.115 23.781,52.462 U4.30@24.714,52.462 ; v1(14.585,25.372) 15.258,25.372 17.075,23.555 U7.2@17.075,22.5
  Bottom w0.165: P1.15@6.33,45.4 7.625,46.695 9.922,46.695 12.324,44.293 12.324,27.62 14.572,25.372 v1(14.585,25.372)
PA6: P1.18 U4.31 U7.4 | length 45.2
  TOP w0.165: P1.18@8.87,42.86 9.612,42.86 10.045,43.293 10.045,43.869 11.207,45.031 11.207,46.404 15.563,50.759 22.548,50.759 23.75,51.962 U4.31@24.714,51.962 ; v1(14.585,23.467) 15.372,23.467 15.775,23.064 U7.4@15.775,22.5
  Bottom w0.165: P1.18@8.87,42.86 10.165,42.86 11.321,41.704 11.321,26.642 14.496,23.467 v1(14.585,23.467)
PA7: P1.17 U4.32 U7.3 | length 53.6
  TOP w0.165: P1.17@6.33,42.86 7.52,41.628 9.886,41.628 10.412,42.154 10.412,43.669 11.588,44.845 11.588,46.327 15.677,50.416 22.688,50.416 23.733,51.462 U4.32@24.714,51.462 ; v1(14.585,24.356) 14.712,24.356 14.776,24.419 15.157,24.419 16.425,23.151 U7.3@16.425,22.5
  Bottom w0.165: P1.17@6.33,42.86 7.562,44.092 10,44.092 11.829,42.263 11.829,27.125 14.585,24.369 v1(14.585,24.356)
PA8: P2.43 U4.67 | length 47.2
  TOP w0.165: U4.67@34.664,40.512 34.664,41.47 35.199,42.005 36.598,42.005 36.598,42.07 v1(37.598,43.069)
  Bottom w0.165: v1(37.598,43.069) 37.598,41.07 40.396,38.272 42.595,38.272 44.328,36.538 44.328,35.139 50.653,28.814 50.653,24.691 53.409,21.935 53.409,13.561 P2.43@57.13,9.84
PA9: C54.1 CN5.1 P2.44 R54.2 U4.68 U6.1 U9.B3 | length 84.3
  TOP w0.165: v1(34.829,39.24) 34.893,39.24 35.164,39.511 U4.68@35.164,40.512 ; CN5.1@38.11,4.95 38.11,6.871 38.506,7.267 v1(38.547,7.267) ; v1(38.197,21.562) 38.26,21.625 U6.1@40.3,21.625 40.3,20.206 40.836,19.67 42.4,19.67 42.616,19.454 ; R54.2@40.7,16.2 41.189,16.2 41.522,16.533 42.373,16.533 ; U9.B3@42.4,15.975 42.373,15.948 42.373,16.533 ; P2.44@59.67,9.84 61.315,11.485 61.315,13.059 60.686,13.688 55.606,13.688 49.002,20.292 v1(47.224,20.292) 43.454,20.292 42.616,19.454 ; 42.373,16.533 42.373,17.18 42.603,17.411 C54.1@42.603,18.45 42.603,19.441 42.616,19.454
  Bottom w0.165: v1(34.829,39.24) 34.829,37.561 36.728,35.662 36.728,34.928 37.407,34.249 37.407,30.427 38.41,29.423 38.41,26.11 37.744,25.443 37.744,21.734 38.197,21.28 v1(38.197,21.562) ; v1(38.547,7.267) 38.547,7.305 39.177,7.935 46.195,7.935 47.305,7.935 48.616,9.246 48.616,10.886 47.821,11.681 47.821,15.491 47.224,16.088 v1(47.224,20.292)
PA10: P2.41 R57.1 U4.69 | length 48.2
  TOP w0.165: U4.69@35.664,40.512 35.664,39.698 35.664,39.104 35.68,39.088 v1(35.667,39.088) ; R57.1@40.55,12.8 40.62,12.87 v1(40.62,14.069) ; v1(46.993,15.083) 51.486,15.083 54.189,12.38 P2.41@57.13,12.38
  Bottom w0.165: v1(35.667,39.088) 35.515,38.936 35.515,37.627 36.023,37.119 36.874,37.119 40.658,33.335 40.658,21.968 42.131,20.495 42.131,15.123 ; v1(40.62,14.069) 41.192,14.069 42.131,15.009 42.131,15.123 ; v1(46.993,15.083) v1(46.993,15.083) 42.169,15.085 42.131,15.123
PA11: R56.2 U4.70 U9.D3 | length 37.4
  TOP w0.165: U4.70@36.164,40.512 36.164,39.354 36.238,39.279 36.238,38.516 v1(36.175,38.453) ; U9.D3@43.4,15.975 43.756,16.331 v1(43.668,16.419) 43.922,16.672 45.23,16.672 cw(c45.23,16.291) 45.611,16.291 45.611,12.774 cw(c45.395,12.774) 45.395,12.558 cw(c45.395,12.837) 45.116,12.837 45.116,13.815 ccw(c44.836,13.815) 44.836,14.094 44.655,14.094 ccw(c44.655,13.79) 44.35,13.79 R56.2@44.35,13.2
  Bottom w0.165: v1(36.175,38.453) 36.594,38.453 41.293,33.754 41.293,22.479 43.668,20.104 v1(43.668,16.419)
PA12: R58.2 U4.71 U9.C3 | length 36.9
  TOP w0.165: v1(36.429,37.691) 36.708,37.97 36.708,39.462 36.664,39.507 U4.71@36.664,40.512 ; U9.C3@42.9,15.975 42.902,15.973 42.902,15.966 42.902,15.975 v1(42.906,16.8) 43.16,17.053 45.256,17.053 cw(c45.255,16.317) 45.992,16.317 45.992,12.737 cw(c45.255,12.737) 45.256,12 R58.2@44.35,12
  Bottom w0.165: v1(36.429,37.691) 36.848,37.691 40.976,33.563 40.976,22.184 42.881,20.279 42.881,16.8 v1(42.906,16.8)
PA13: P2.42 SB9.1 U4.72 | length 88.9
  TOP w0.165: U4.72@37.164,40.512 37.164,41.87 37.563,42.27 v1(38.397,42.27) ; v1(45.594,34.873) 45.594,35.062 46.013,35.481 48.088,35.481 51.428,38.821 51.428,39.583 51.872,40.028 51.872,59.103 52.558,59.789 v1(52.558,69.06)
  Bottom w0.165: v1(38.397,42.27) 38.385,42.257 38.385,40.883 40.596,38.671 42.795,38.671 44.684,36.782 44.684,35.383 45.194,34.873 v1(45.594,34.873) 45.594,34.474 51.034,29.033 51.034,24.756 53.726,22.063 53.726,16.199 56.241,13.684 58.366,13.684 P2.42@59.67,12.38 ; v1(52.558,69.06) 54.184,69.06 56.508,71.384 56.508,72.501 SB9.1@56.199,72.501
PA14: P2.39 SB5.1 U4.76 | length 87.3
  TOP w0.165: v1(40.196,41.87) 40.196,42.27 40.614,42.27 U4.76@40.614,42.362 ; v1(46.462,34.897) 48.113,34.897 51.79,38.574 51.79,39.4 52.202,39.812 52.202,47.318 52.202,58.9 53.117,59.814 v1(53.117,67.587)
  Bottom w0.165: v1(40.196,41.87) 40.418,41.87 42.206,40.081 44.618,40.081 46.462,38.237 v1(46.462,34.897) 46.462,34.199 51.415,29.246 51.415,24.82 54.044,22.191 54.044,16.8 55.924,14.92 P2.39@57.13,14.92 ; v1(53.117,67.587) 53.209,67.679 54.314,67.679 57.765,71.13 57.765,76.998 57.163,77.6 SB5.1@56.199,77.581
PA15: P2.40 U4.77 | length 38.9
  TOP w0.165: U4.77@40.614,42.962 41.596,42.962 41.796,42.762 v1(41.796,41.47)
  Bottom w0.165: v1(41.796,41.47) 42.795,40.471 44.794,40.471 47.193,38.072 47.193,34.039 51.796,29.436 51.796,24.885 54.361,22.319 54.361,18.09 56.368,16.083 58.507,16.083 P2.40@59.67,14.92
PB0: P1.22 U4.35 | length 23.5
  TOP w0.165: P1.22@8.87,37.78 8.883,37.78 11.611,40.508 11.611,43.069 12.731,44.189 12.731,46.098 16.033,49.4 23.145,49.4 23.675,49.931 24.174,49.931 24.204,49.962 U4.35@24.714,49.962
PB1: P1.21 U4.36 | length 27.7
  TOP w0.165: P1.21@6.33,37.78 7.637,36.473 9.391,36.473 12.011,39.093 12.011,42.869 13.112,43.97 13.112,46.022 16.15,49.06 23.3,49.06 23.702,49.462 U4.36@24.714,49.462
PB2: P1.24 R30.2 R31.1 U4.37 | length 23.9
  TOP w0.165: P1.24@8.87,35.24 8.87,35.466 12.411,39.006 12.411,42.669 16.141,46.4 R30.2@17.785,46.4 ; R30.2@17.75,46.35 17.75,46.365 R30.2@17.785,46.4 ; U4.37@24.714,48.962 23.697,48.962 21.135,46.4 R30.2@17.785,46.4
PB3: P2.28 SB15.2 U4.89 | length 72.9
  TOP w0.165: U4.89@40.614,48.962 42.395,48.962 44.141,47.216 v1(44.43,47.216) ; v1(50.991,42.27) 51.44,42.72 51.44,59.205 51.961,59.725 51.974,59.713 51.974,65.834 51.44,66.368 v1(51.44,67.282)
  Bottom w0.165: SB15.2@37.25,68.85 37.256,68.856 50.933,68.856 51.44,68.349 v1(51.44,67.282) ; v1(44.43,47.216) v1@44.245,47.216 ; P2.28@59.67,30.16 58.355,31.475 56.615,31.475 51.99,36.1 51.99,41.27 v1(50.991,42.27) 50.959,42.314 50.391,42.882 50.391,45.143 48.867,46.667 44.794,46.667 44.338,47.124 v1@44.245,47.216 ; v1@44.245,47.216 44.194,47.216 44.194,47.267 v1@44.245,47.216
PB4: P2.25 U4.90 | length 27.9
  TOP w0.165: U4.90@40.614,49.462 42.395,49.462 43.892,47.965 44.176,47.965 v1(44.176,47.978)
  Bottom w0.165: v1(44.176,47.978) 44.506,47.978 45.417,47.067 49.076,47.067 50.791,45.353 50.791,43.469 52.39,41.87 52.39,36.271 55.962,32.7 P2.25@57.13,32.7
PB5: P2.26 U4.91 | length 30.6
  TOP w0.165: U4.91@40.614,49.962 42.522,49.962 43.744,48.74 v1(43.922,48.74)
  Bottom w0.165: v1(43.922,48.74) 44.278,48.74 45.551,47.467 49.286,47.467 51.191,45.562 51.191,43.669 52.79,42.07 52.79,36.443 55.25,33.983 58.387,33.983 P2.26@59.67,32.7
PB6: P2.23 R32.2 U4.92 U5.1 U8.2 | length 84.2
  TOP w0.165: v1(21.57,24.483) 21.57,23.915 22.653,22.832 23.301,22.832 24.135,21.998 U8.2@24.88,21.95 ; v1(28.174,51.432) 29.145,50.462 U4.92@40.614,50.462 42.595,50.462 43.695,49.362 44.443,49.362 v1(45.065,48.74) 45.398,48.407 45.398,47.9 R32.2@46.1,47.9 ; v1(30.079,32.865) 30.079,32.389 31.124,31.344 32.148,31.344 U5.1@32.706,31.901
  Bottom w0.165: v1(21.57,24.483) 21.57,24.432 23.031,24.432 23.793,25.194 26.142,25.194 26.879,25.931 26.879,29.271 30.079,32.471 v1(30.079,32.865) 29.774,33.17 29.774,37.081 30.028,37.335 30.028,37.488 30.028,39.215 28.974,40.269 28.974,44.251 28.003,45.222 28.003,51.432 v1(28.174,51.432) ; v1(45.065,48.74) 45.344,48.74 46.297,47.787 49.6,47.787 51.591,45.797 51.591,43.869 53.19,42.27 53.19,36.805 54.755,35.24 P2.23@57.13,35.24
PB7: P2.24 U4.93 | length 29.8
  TOP w0.165: U4.93@40.614,50.962 42.945,50.962 43.008,50.899 v1(43.033,50.899)
  Bottom w0.165: v1(43.033,50.899) 43.198,50.899 44.824,49.273 45.586,49.273 46.716,48.143 50.028,48.143 51.907,46.263 51.907,44.152 53.59,42.469 53.59,37.358 54.475,36.473 58.437,36.473 P2.24@59.67,35.24
PB8: P2.19 U4.95 | length 24.6
  TOP w0.165: U4.95@40.614,51.962 42.915,51.962 43.274,52.321 47.84,52.321 v1(47.992,52.169)
  Bottom w0.165: v1(47.992,52.169) 50.082,52.169 53.756,48.494 53.756,44.701 55.189,43.269 55.189,41.918 56.787,40.32 P2.19@57.13,40.32
PB9: P2.20 R27.2 U4.96 U5.4 U8.1 | length 86.4
  TOP w0.165: v1(22.459,23.848) 22.459,23.886 22.484,23.861 22.864,23.861 24.275,22.45 U8.1@24.88,22.45 ; v1(29.063,51.585) 29.863,50.785 38.207,50.785 39.884,52.462 U4.96@40.614,52.462 42.738,52.462 42.928,52.652 47.097,52.652 47.428,52.982 47.711,52.982 47.792,53.064 v1(47.992,53.064) 47.992,53.05 R27.2@49,53.05 ; v1(31.674,28.572) 34.206,31.104 U5.4@34.206,31.901
  Bottom w0.165: v1(22.459,23.848) 22.497,23.886 22.954,23.886 23.907,24.839 26.345,24.839 27.196,25.689 27.196,27.813 27.955,28.572 ; v1(29.063,51.585) 29.063,51.458 28.402,50.797 28.402,45.426 29.292,44.536 29.292,40.663 29.571,40.383 29.609,40.345 30.358,39.596 30.358,37.208 30.181,37.031 30.181,34.364 30.714,33.83 30.714,32.23 27.955,29.471 27.955,28.572 ; v1(31.674,28.572) 27.955,28.572 ; v1(47.992,53.064) 49.694,53.064 54.153,48.606 54.153,44.905 55.588,43.469 55.588,42.469 56.388,41.67 58.387,41.67 59.67,40.387 P2.20@59.67,40.32
PB10: P1.34 U4.47 U10.3 | length 102.3
  TOP w0.165: P1.34@8.87,22.54 9.721,22.54 11.283,24.102 11.283,28.344 13.366,30.427 13.366,35.507 16.408,38.549 16.408,40.81 17.239,41.641 21.303,41.641 23.624,43.962 U4.47@24.714,43.962 ; U10.3@48.133,7.62 U10.3@48.133,7.211 48.133,6.858 48.422,6.569 48.429,6.569 48.592,6.406 v1(48.592,5.207)
  Bottom w0.165: P1.34@8.87,22.54 7.638,21.308 5.466,21.308 4.336,20.178 4.336,4.493 5.289,3.541 9.873,3.541 12.667,6.335 21.443,6.335 22.144,5.634 31.349,5.634 32.695,4.288 41.491,4.288 41.826,4.623 48.008,4.623 v1(48.592,5.207)
PB12: P1.36 U4.51 | length 31.4
  TOP w0.165: v1(24.872,39.596) 26.371,39.596 26.564,39.789 U4.51@26.564,40.512
  Bottom w0.165: P1.36@8.87,20 10.165,20 12.413,22.248 15.093,22.248 15.728,22.883 15.728,26.858 16.477,27.607 16.477,31.785 24.288,39.596 v1(24.872,39.596)
PB13: P1.37 U4.52 | length 35.6
  TOP w0.165: v1(24.77,38.783) 26.249,38.783 27.164,39.698 U4.52@27.164,40.512
  Bottom w0.165: P1.37@6.33,17.46 7.536,18.666 9.556,18.666 12.769,21.879 15.17,21.879 16.058,22.768 16.058,26.693 16.795,27.429 16.795,31.519 24.059,38.783 v1(24.77,38.783)
PB14: P1.38 U4.53 | length 33.4
  TOP w0.165: v1(24.288,37.996) 25.964,37.996 27.664,39.695 U4.53@27.664,40.512
  Bottom w0.165: P1.38@8.87,17.46 12.896,21.486 15.258,21.486 15.779,22.006 16.401,22.629 16.401,26.54 17.125,27.264 17.125,31.214 22.332,36.421 23.932,38.021 24.262,38.021 v1(24.288,37.996)
PB15: P1.39 U4.54 | length 38.4
  TOP w0.165: v1(24.491,37.183) 25.659,37.183 28.164,39.687 U4.54@28.164,40.512
  Bottom w0.165: P1.39@6.33,14.92 7.631,16.221 9.734,16.221 10.635,17.122 10.635,18.641 13.099,21.105 15.408,21.105 16.757,22.454 16.757,26.413 17.442,27.099 17.442,30.998 23.627,37.183 v1(24.491,37.183)
PC0: P1.8 R42.1 U4.15 | length 65
  TOP w0.165: U4.15@31.664,56.412 31.664,55.3 32,54.964 v1(32,54.9) ; v1(37.826,28.166) 40.049,28.166 40.391,27.823 43.681,27.823 44,27.504 R42.1@44,26.9
  Bottom w0.165: P1.8@8.87,55.56 10.412,55.56 14.112,59.261 22.605,59.261 24.922,56.944 30.27,56.944 32,55.214 v1(32,54.9) 32,54.176 33.4,52.776 33.4,51.648 32.81,51.058 32.81,42.657 33.4,42.066 33.4,38.437 36.347,35.489 36.347,34.569 36.855,34.061 36.855,30.099 37.826,29.128 v1(37.826,28.166)
PC1: P1.7 U4.16 | length 31.1
  TOP w0.165: U4.16@31.164,56.412 31.164,54.736 v1(31.2,54.7)
  Bottom w0.165: P1.7@6.33,55.56 7.613,54.277 7.999,54.277 8.013,54.263 9.644,54.263 14.241,58.861 22.405,58.861 24.767,56.5 29.977,56.5 31.2,55.277 v1(31.2,54.7)
PC2: P1.10 U4.17 | length 27.4
  TOP w0.165: v1(30.4,54.9) 30.4,55.037 30.664,55.3 U4.17@30.664,56.412
  Bottom w0.165: P1.10@8.87,53.02 9.429,53.02 10.8,54.391 10.8,54.899 14.42,58.519 22.148,58.519 24.567,56.1 29.513,56.1 30.4,55.213 v1(30.4,54.9)
PC3: P1.9 R53.2 U4.18 U10.4 | length 92.7
  TOP w0.165: v1(29.6,55.1) 29.963,55.3 30.164,55.5 U4.18@30.164,56.412 ; R53.2@39.2,15.7 39.2,16.198 39.477,16.475 v1(39.477,16.482) ; v1(47.879,10.553) 48.299,10.553 48.616,10.236 48.616,9.347 48.133,8.865 U10.4@48.133,8.561
  Bottom w0.165: P1.9@6.33,53.02 7.569,51.781 9.823,51.781 11.248,53.206 11.248,54.839 14.61,58.201 21.866,58.201 24.367,55.7 29,55.7 v1(29.6,55.1) 29.6,54.743 30.257,54.087 31.171,54.087 32.111,53.147 32.111,42.199 32.695,41.615 32.695,37.539 36.2,34.033 36.2,29.941 36.728,29.413 36.728,19.231 v1(39.477,16.482) 39.452,16.457 39.452,10.919 40.836,9.535 44.557,9.535 46.198,11.176 47.256,11.176 v1(47.879,10.553)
